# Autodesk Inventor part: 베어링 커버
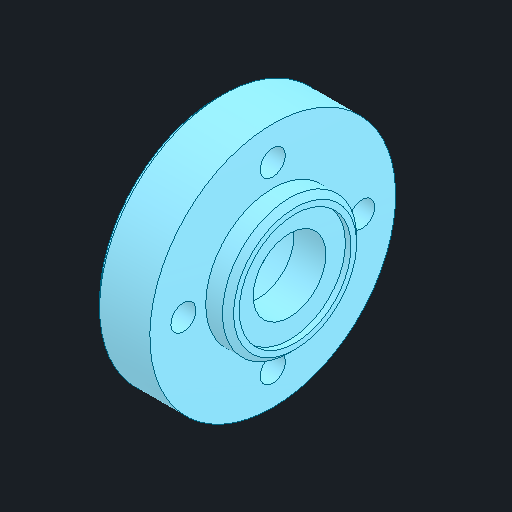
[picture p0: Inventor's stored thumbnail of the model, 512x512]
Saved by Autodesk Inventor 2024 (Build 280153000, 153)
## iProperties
Created: 2024-05
Part Number: 베어링 커버
Material: 강철, 연강
Document SubType Name: Modeling
Designer: kh_501
Density: 7.85 g/cm^3
Appearance: 기본값
Author: jhkim
Sending System: Autodesk Inventor 2025
Preprocessor: ST-DEVELOPER v20
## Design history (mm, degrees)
feature "솔리드1"
node "솔리드2"
